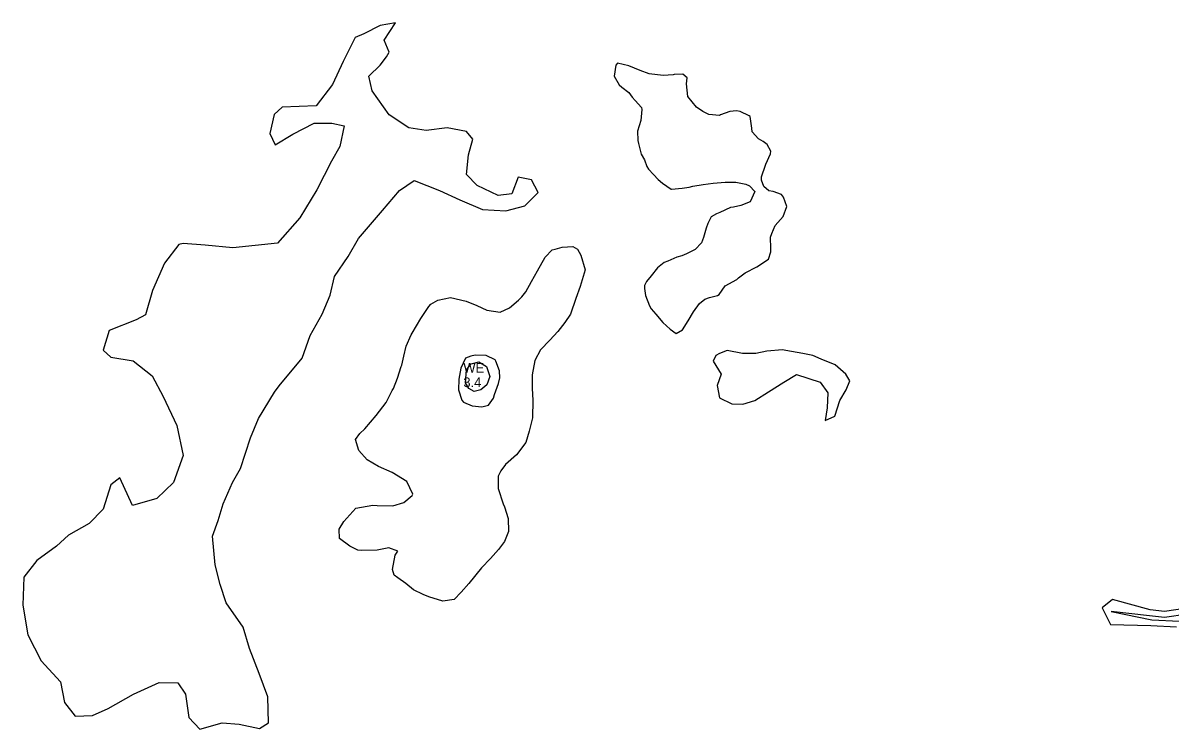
# Model space of a CAD drawing. Extents: x 2160437 to 2172832, y 205694 to 212444.
# Drawn here: x 2166573 to 2167169, y 209458 to 209825 of the extents above; entities that cross this region are included whole.
import ezdxf

# ---------------------------------------------------------------- set-up
doc = ezdxf.new("R2010")
doc.units = 0
for name, color, linetype in [('RD_EX_H2O_Pond', 7, 'Continuous'), ('RD_EX_H2O_txCode', 7, 'Continuous'), ('RD_EX_VEG_ShrubLine', 7, 'Continuous'), ('RD_EX_VEG_TreeLine', 7, 'Continuous')]:
    doc.layers.add(name, color=color, linetype=linetype)

msp = doc.modelspace()

# ---------------------------------------------------------------- linework, layer by layer
at = {"layer": 'RD_EX_H2O_Pond'}
msp.add_lwpolyline([(2166802.96, 209637.93), (2166803.47, 209644.67), (2166805.84, 209647.8), (2166809.73, 209648.7), (2166813.84, 209646.36), (2166815.47, 209641.18), (2166814.03, 209636.91), (2166810.9, 209634.23), (2166807.4, 209633.4), (2166804.6, 209634.91)], close=True, dxfattribs=at)
msp.add_lwpolyline([(2167177.92, 209517.88), (2167165.93, 209516.16), (2167158.18, 209517.06), (2167138.14, 209519.18), (2167159.25, 209514.89), (2167173.72, 209514.24)], dxfattribs=at)
at = {"layer": 'RD_EX_VEG_ShrubLine'}
for points in [[(2166750.08, 209819.03), (2166745.55, 209816.98), (2166739.38, 209804.62), (2166733.88, 209792.68), (2166725.41, 209781.6), (2166707.69, 209780.93), (2166703.53, 209777.04), (2166701.28, 209767.24), (2166704.06, 209761.42), (2166713.16, 209766.93), (2166724.25, 209772.63), (2166733.47, 209772.56), (2166739.81, 209771.15), (2166737.68, 209760.57), (2166733.29, 209752.94), (2166725.75, 209738.07), (2166716.88, 209723.45), (2166716.88, 209723.45), (2166705.24, 209710.42), (2166682.11, 209707.87), (2166667.73, 209709.3), (2166656.32, 209710.11), (2166654.04, 209709.58), (2166646.58, 209699.96), (2166640.29, 209685.73), (2166636.68, 209673.18), (2166631.79, 209670.58), (2166617.75, 209665.01), (2166614.63, 209654.88), (2166618.65, 209651.27), (2166630.25, 209649.29), (2166640.22, 209641.55), (2166645.85, 209630.84), (2166652.98, 209615.74), (2166656.21, 209600.23), (2166651.29, 209586.1), (2166642.55, 209577.91), (2166630, 209574.31), (2166623.44, 209588.56), (2166618.78, 209584.89), (2166614.78, 209572.27), (2166607.48, 209564.87), (2166596.79, 209558.75), (2166590.45, 209553.19), (2166580.25, 209545.77), (2166573.55, 209537.02), (2166573.05, 209522.58), (2166575.59, 209507.14), (2166582.56, 209493.55), (2166592.61, 209482.77), (2166594.71, 209471.97), (2166600.2, 209464.94), (2166609.25, 209465.3), (2166617.39, 209468.97), (2166630.43, 209476.31), (2166643.72, 209482.34), (2166653.43, 209482.29), (2166657.49, 209476.38), (2166659.26, 209464.29), (2166664.94, 209458.24), (2166676.58, 209461.41), (2166685.33, 209460.83), (2166695.92, 209458.47), (2166700.65, 209461.5), (2166700.21, 209474.92), (2166695.8, 209487), (2166690.71, 209499.98), (2166687.42, 209511.08), (2166678.57, 209523.71), (2166675.54, 209533.25), (2166672.82, 209543.48), (2166671.54, 209558.24), (2166674.49, 209566.4), (2166677.08, 209575.08), (2166681.83, 209586.16), (2166685.95, 209593.44), (2166691.19, 209609.34), (2166695.45, 209619.32), (2166703.77, 209632.99), (2166706.13, 209636.37), (2166718.1, 209650.68), (2166722.19, 209662.42), (2166728.51, 209673.51), (2166732.62, 209683.44), (2166734.78, 209693.04), (2166741.96, 209703.38), (2166747.37, 209712.72), (2166759.82, 209727.29), (2166768.57, 209737.65), (2166776.3, 209742.82), (2166789.36, 209737.66), (2166799.9, 209732.79), (2166811.72, 209727.82), (2166823.87, 209727.04), (2166833.71, 209729.69), (2166840.59, 209736.69), (2166837.18, 209743.27), (2166830.21, 209744.6), (2166826.89, 209735.89), (2166819.81, 209735.11), (2166808.92, 209740.26), (2166803.44, 209745.97), (2166804.44, 209756.21), (2166806.62, 209764.24), (2166803.42, 209768.33), (2166793.44, 209770.18), (2166782.46, 209768.76), (2166773.48, 209770.16), (2166763.16, 209776.85), (2166754.37, 209789.34), (2166752.74, 209796.93), (2166758.58, 209802.7), (2166761.84, 209807), (2166763.21, 209809.51), (2166760.71, 209815.68), (2166766.52, 209824.6), (2166758.49, 209823.29)], [(2166892.28, 209768.46), (2166892.42, 209763.58), (2166892.73, 209762), (2166894.18, 209756.54), (2166895.92, 209753.6), (2166897.09, 209750.07), (2166897.91, 209748.68), (2166900.44, 209745.91), (2166903, 209743.32), (2166905.11, 209741.47), (2166909.65, 209738.34), (2166909.92, 209738.28), (2166915.46, 209738.85), (2166919.07, 209739.39), (2166920.92, 209739.88), (2166926.25, 209740.78), (2166931.54, 209741.46), (2166931.54, 209741.46), (2166937.79, 209742.01), (2166943.21, 209742.03), (2166943.21, 209742.03), (2166948.47, 209741.04), (2166950.45, 209740.09), (2166953.07, 209737.11), (2166950.71, 209731.74), (2166950.71, 209731.74), (2166945.89, 209729.83), (2166942, 209729.06), (2166940.44, 209728.8), (2166934.97, 209726.27), (2166933.19, 209725.64), (2166930.48, 209724.03), (2166930.48, 209724.03), (2166928.73, 209720.56), (2166927.8, 209718.21), (2166926.43, 209713.3), (2166925.51, 209710.59), (2166922.2, 209706.98), (2166917.7, 209704.74), (2166915.17, 209703.78), (2166912.6, 209703.01), (2166907.92, 209701.03), (2166906.06, 209700.37), (2166902.6, 209697.61), (2166899.33, 209693.43), (2166896.9, 209690.44), (2166895.88, 209688.44), (2166895.9, 209686.87), (2166896.31, 209683.25), (2166898.52, 209677.88), (2166899.34, 209676.24), (2166901.66, 209673.52), (2166905.29, 209669.18), (2166905.29, 209669.18), (2166909.23, 209665.66), (2166912.36, 209663.53), (2166915.5, 209665.3), (2166915.5, 209665.3), (2166918.47, 209670.03), (2166921.37, 209674.73), (2166921.37, 209674.73), (2166924.41, 209679.07), (2166927.11, 209681.22), (2166929.6, 209682.2), (2166933.68, 209683.12), (2166934.59, 209683.68), (2166937.69, 209688.17), (2166943.83, 209691.53), (2166944.7, 209692.4), (2166948.11, 209694.89), (2166954.11, 209698.07), (2166960.27, 209702.02), (2166961.37, 209705.92), (2166961.42, 209707.63), (2166961.36, 209713.37), (2166961.94, 209715.33), (2166963.73, 209719.57), (2166967.94, 209724.1), (2166969.74, 209729.3), (2166969.74, 209729.3), (2166968.02, 209734.28), (2166967, 209735.64), (2166962.75, 209737.13), (2166960.41, 209737.53), (2166957.87, 209739.75), (2166956.68, 209742.99), (2166956.66, 209744.8), (2166958.62, 209750.77), (2166958.84, 209751.39), (2166961.33, 209756.64), (2166961.44, 209758.09), (2166959.56, 209761.52), (2166957.53, 209763.15), (2166955.07, 209764.5), (2166951.74, 209768.04), (2166951.52, 209770.07), (2166950.66, 209776.04), (2166950.23, 209776.41), (2166945.46, 209778.62), (2166943.62, 209779.09), (2166940.23, 209778.63), (2166935.3, 209776.89), (2166934.85, 209776.67), (2166929.31, 209777.06), (2166926.06, 209778.65), (2166922.86, 209780.87), (2166918.37, 209786.38), (2166918.37, 209786.38), (2166917.64, 209793.02), (2166917.98, 209796.17), (2166915.77, 209798.06), (2166911.24, 209797.88), (2166910.7, 209797.76), (2166905.55, 209797.26), (2166898.3, 209798.24), (2166898.3, 209798.24), (2166893.58, 209799.89), (2166887.7, 209802.3), (2166887.7, 209802.3), (2166881.8, 209803.75), (2166880.96, 209802.69), (2166880.16, 209797.04), (2166880.16, 209797.04), (2166882.63, 209792.51), (2166884.14, 209791.34), (2166887.67, 209788.49), (2166889.48, 209786.12), (2166890.92, 209784.39), (2166894.23, 209780.79), (2166894.42, 209779.62), (2166893.96, 209774.06), (2166893.96, 209774.06)], [(2166934.86, 209653.17), (2166932.9, 209652.01), (2166931.54, 209649.14), (2166935.67, 209642.34), (2166933.61, 209636.55), (2166934.76, 209630.17), (2166941.27, 209626.96), (2166946.89, 209626.84), (2166953.22, 209628.7), (2166960.31, 209633.2), (2166968.12, 209638.19), (2166974.83, 209642.25), (2166986.99, 209638.16), (2166991.08, 209632.62), (2166990.76, 209624.92), (2166989.73, 209618.28), (2166994.67, 209620.65), (2166997.31, 209628.79), (2167000.51, 209634.19), (2167002.5, 209638.84), (2167000.46, 209642.32), (2166994.95, 209647.19), (2166987.55, 209650.24), (2166983.22, 209652.08), (2166978.15, 209653.14), (2166969.16, 209654.6), (2166967.49, 209655.05), (2166959.42, 209654.29), (2166953.63, 209653.06), (2166946.82, 209653.16), (2166938.77, 209654.64)]]:
    msp.add_lwpolyline(points, close=True, dxfattribs=at)
msp.add_lwpolyline([(2167177.73, 209520.88), (2167165.89, 209519.18), (2167158.51, 209520.04), (2167138.86, 209525.41), (2167133.47, 209521.14), (2167137.8, 209512.45), (2167158.88, 209511.91), (2167172.1, 209511.31)], dxfattribs=at)
at = {"layer": 'RD_EX_VEG_TreeLine'}
for points in [[(2166779.74, 209671.21), (2166783.8, 209677.56), (2166784.83, 209678.77), (2166788.48, 209680.74), (2166795.09, 209682.08), (2166795.09, 209682.08), (2166803.26, 209680.21), (2166808.79, 209678.08), (2166808.79, 209678.08), (2166813.89, 209675.54), (2166820.89, 209674.55), (2166820.89, 209674.55), (2166825.65, 209676.85), (2166830.44, 209680.82), (2166832.14, 209682.45), (2166834.19, 209685.14), (2166837.21, 209690.5), (2166840.32, 209696.07), (2166840.32, 209696.07), (2166844.3, 209703.05), (2166847.92, 209706.82), (2166849.43, 209707.23), (2166853.12, 209708.21), (2166858.54, 209708.53), (2166861.1, 209707.26), (2166862.84, 209704.19), (2166865.06, 209696.58), (2166862.47, 209687.9), (2166860.22, 209681.58), (2166860.22, 209681.58), (2166857.41, 209673.47), (2166854.4, 209669.19), (2166850.82, 209664.43), (2166850.82, 209664.43), (2166846.68, 209660.05), (2166841.88, 209655), (2166838.87, 209649.39), (2166838.87, 209649.39), (2166837.5, 209642.07), (2166837.44, 209635.01), (2166837.89, 209628.8), (2166837.89, 209628.8), (2166837.72, 209619.63), (2166835.94, 209612.74), (2166834.27, 209606.89), (2166834.27, 209606.89), (2166829.33, 209600.46), (2166823.7, 209595.43), (2166821.18, 209592.24), (2166819.78, 209589.38), (2166819.93, 209583.06), (2166822.36, 209575.12), (2166823.07, 209573.48), (2166825.07, 209567.53), (2166825.15, 209560.77), (2166823.16, 209555.54), (2166823.16, 209555.54), (2166820.09, 209551.4), (2166815.92, 209546.67), (2166811.25, 209541.92), (2166804.57, 209533.75), (2166804.57, 209533.75), (2166800.59, 209529.18), (2166797.01, 209525.51), (2166797.01, 209525.51), (2166791.07, 209524.58), (2166783.82, 209526.88), (2166780.83, 209527.99), (2166775.83, 209530.48), (2166771.87, 209533.71), (2166767.73, 209536.77), (2166765.76, 209538.02), (2166764.96, 209541.03), (2166766.37, 209548.44), (2166767.81, 209550.56), (2166763.03, 209552.23), (2166757, 209551.1), (2166748.82, 209550.82), (2166747, 209551.04), (2166742.75, 209553.07), (2166737.38, 209557.17), (2166737.29, 209562.02), (2166739.77, 209565.95), (2166745.92, 209572.91), (2166754.78, 209574.45), (2166756.99, 209574.29), (2166765.09, 209574.13), (2166770.9, 209575.83), (2166775.27, 209579.39), (2166775.48, 209580.14), (2166772.42, 209586.68), (2166764.78, 209591.33), (2166757.69, 209594.52), (2166751.87, 209597.86), (2166751.87, 209597.86), (2166747.5, 209602.83), (2166745.75, 209608.55), (2166747.93, 209611.53), (2166750.58, 209613.94), (2166756.52, 209621), (2166761.69, 209627.68), (2166761.69, 209627.68), (2166764.83, 209633.84), (2166765.42, 209634.89), (2166767.51, 209640.32), (2166769.52, 209646.38), (2166769.83, 209647.08), (2166770.92, 209651.64), (2166772.13, 209656.98), (2166774.74, 209662.77), (2166775.24, 209663.63)], [(2166813.62, 209651.99), (2166807.87, 209652.3), (2166805.58, 209651.76), (2166802.83, 209650.72), (2166800.49, 209645.53), (2166800.49, 209645.53), (2166799.35, 209639.79), (2166799.28, 209634.3), (2166799.28, 209634.3), (2166801.02, 209628.83), (2166801.79, 209627.88), (2166806.43, 209625.91), (2166811.36, 209625.38), (2166814.9, 209626.3), (2166817.35, 209629.88), (2166818.01, 209631.87), (2166819.94, 209637.49), (2166820.7, 209640.51), (2166820.5, 209644.08), (2166818.58, 209649.15), (2166818.26, 209649.78)]]:
    msp.add_lwpolyline(points, close=True, dxfattribs=at)

# ---------------------------------------------------------------- texts
at = {"layer": 'RD_EX_H2O_txCode'}
for s, p in [('WE', (2166801.79, 209643.16)), ('3.4', (2166801.79, 209635.66))]:
    msp.add_text(s, height=5, dxfattribs=at).set_placement(p)

doc.saveas('drawing.dxf')
